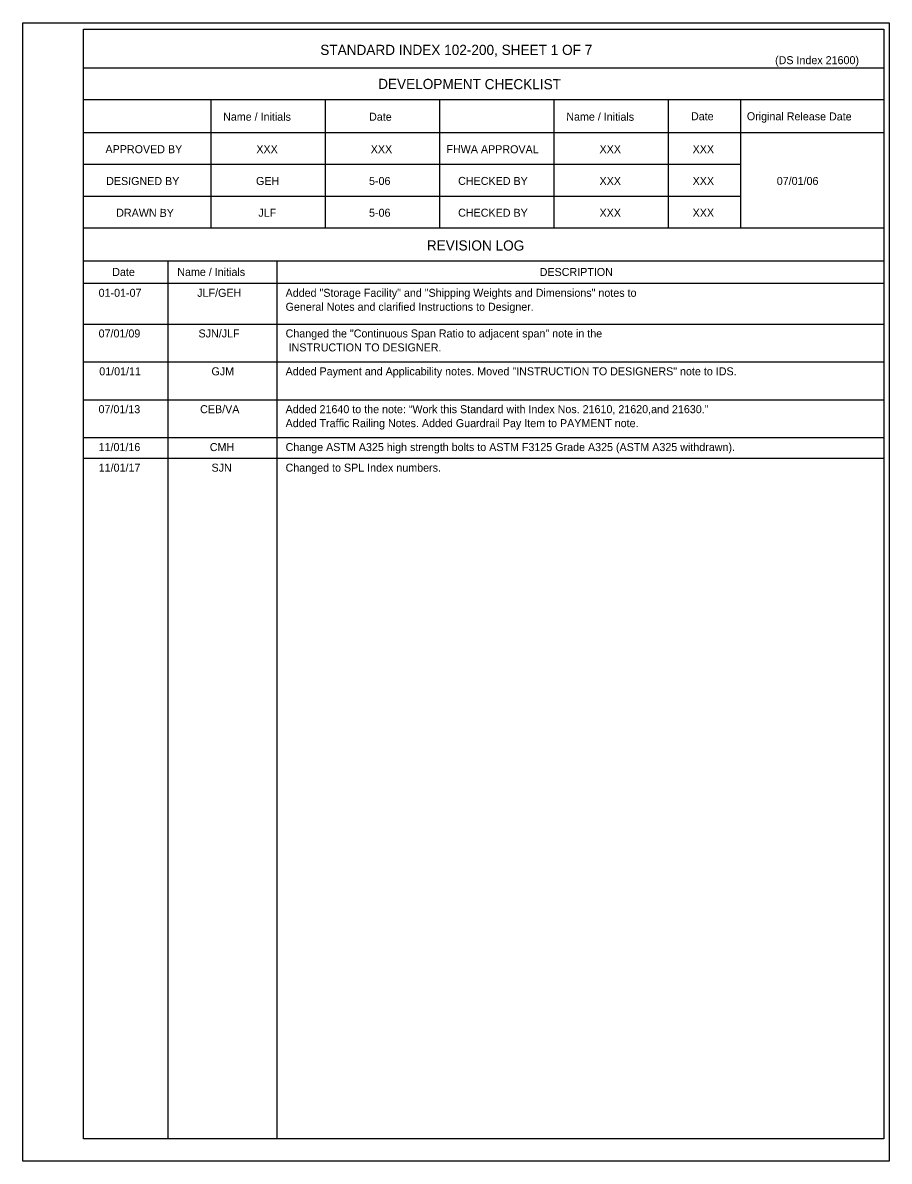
# Model space of a CAD drawing. Extents: x 0 to 2.25, y -0.21 to 0.88.
# Drawn here: x 1.572 to 2.254, y -0.02 to 0.875 of the extents above; entities that cross this region are included whole.
import ezdxf

# ---------------------------------------------------------------- set-up
doc = ezdxf.new("R2010")
doc.units = 0
for name, color, linetype in [('Border', 7, 'Continuous'), ('Dimension', 7, 'Continuous'), ('PlotBorder_dp', 7, 'Continuous'), ('TextStructures', 7, 'Continuous')]:
    doc.layers.add(name, color=color, linetype=linetype)

msp = doc.modelspace()

# ---------------------------------------------------------------- linework, layer by layer
at = {"layer": 'Border'}
for p, q in [((2.24963, 0.83971), (1.62004, 0.83971)), ((2.24963, 0.81471), (1.62004, 0.81471)), ((1.72004, 0.81471), (1.72004, 0.71384)), ((1.81004, 0.81471), (1.81004, 0.71384)), ((1.90004, 0.81471), (1.90004, 0.71384)), ((1.99004, 0.81471), (1.99004, 0.71384)), ((2.08004, 0.81471), (2.08004, 0.71384)), ((2.13676, 0.81471), (2.13676, 0.71384)), ((2.24963, 0.78884), (1.62004, 0.78884)), ((2.13676, 0.76384), (1.62004, 0.76384)), ((2.13676, 0.73884), (1.62004, 0.73884)), ((2.24963, 0.71384), (1.62004, 0.71384)), ((2.24963, 0.68797), (1.62004, 0.68797)), ((1.6863, 0.68797), (1.6863, -0.00286)), ((1.772, 0.68797), (1.772, -0.00286)), ((2.24963, 0.67035), (1.62004, 0.67035))]:
    msp.add_line(p, q, dxfattribs=at)
msp.add_lwpolyline([(1.62005, 0.87035), (2.24963, 0.87035), (2.24963, -0.00286), (1.62005, -0.00286)], close=True, dxfattribs=at)
at = {"layer": 'Dimension'}
for p, q in [((1.62005, 0.63838), (2.24963, 0.63838)), ((1.62005, 0.60858), (2.24963, 0.60858)), ((1.62005, 0.57878), (2.24963, 0.57878)), ((1.62005, 0.54897), (2.24963, 0.54897)), ((1.62005, 0.53277), (2.24963, 0.53277))]:
    msp.add_line(p, q, dxfattribs=at)
at = {"layer": 'PlotBorder_dp'}
msp.add_line((1.57221, -0.0204), (1.57221, -0.0204), dxfattribs=at)
msp.add_lwpolyline([(1.57221, 0.87543), (2.25388, 0.87543), (2.25388, -0.0204), (1.57221, -0.0204)], close=True, dxfattribs=at)

# ---------------------------------------------------------------- texts
at = {"layer": 'TextStructures'}
for s, height, p in [('STANDARD INDEX 102-200, SHEET 1 OF 7', 0.008, (1.80626, 0.8501)), ('(DS Index 21600)', 0.0063, (2.16407, 0.84285)), ('XXX', 0.0063, (1.75598, 0.7728)), ('XXX', 0.0063, (1.84598, 0.7728)), ('XXX', 0.0063, (2.02598, 0.7728)), ('XXX', 0.0063, (2.09921, 0.7728)), ('GEH', 0.0063, (1.75573, 0.7478)), ('5-06', 0.0063, (1.84463, 0.7478)), ('XXX', 0.0063, (2.02598, 0.7478)), ('XXX', 0.0063, (2.09921, 0.7478)), ('07/01/06', 0.0063, (2.1654, 0.7478)), ('JLF', 0.0063, (1.75753, 0.7228)), ('5-06', 0.0063, (1.84463, 0.7228)), ('XXX', 0.0063, (2.02598, 0.7228)), ('XXX', 0.0063, (2.09921, 0.7228)), ('DESCRIPTION', 0.0063, (1.9789, 0.67619)), ('01-01-07', 0.0063, (1.63189, 0.65979)), ('JLF/GEH', 0.0063, (1.70947, 0.65979)), ('Added "Storage Facility" and "Shipping Weights and Dimensions" notes to ', 0.0063, (1.77898, 0.65979)), ('General Notes and clarified Instructions to Designer. ', 0.0063, (1.77898, 0.6488)), ('07/01/09', 0.0063, (1.63189, 0.62782)), ('SJN/JLF', 0.0063, (1.71049, 0.62782)), ('Changed the "Continuous Span Ratio to adjacent span" note in the ', 0.0063, (1.77899, 0.62782)), (' INSTRUCTION TO DESIGNER.', 0.0063, (1.77899, 0.61683)), ('01/01/11', 0.0063, (1.63239, 0.59802)), ('GJM', 0.0063, (1.72066, 0.59802)), ('Added Payment and Applicability notes. Moved "INSTRUCTION TO DESIGNERS" note to IDS.', 0.0063, (1.77899, 0.59802)), ('07/01/13', 0.0063, (1.63182, 0.56821)), ('CEB/VA', 0.0063, (1.71174, 0.56821)), ('Added 21640 to the note: “Work this Standard with Index Nos. 21610, 21620,and 21630.”', 0.0063, (1.77899, 0.56821)), ('Added Traffic Railing Notes. Added Guardrail Pay Item to PAYMENT note.', 0.0063, (1.77899, 0.55722)), ('11/01/16', 0.0063, (1.63189, 0.53841)), ('CMH', 0.0063, (1.71937, 0.53841)), ('Change ASTM A325 high strength bolts to ASTM F3125 Grade A325 (ASTM A325 withdrawn).', 0.0063, (1.77899, 0.53841)), ('11/01/17', 0.0063, (1.63196, 0.52221)), ('SJN', 0.0063, (1.72071, 0.52221)), ('Changed to SPL Index numbers.', 0.0063, (1.77899, 0.52221))]:
    msp.add_text(s, height=height, dxfattribs=at).set_placement(p)
for s, height, p in [('DEVELOPMENT CHECKLIST', 0.008, (1.85179, 0.82336)), ('Name / Initials', 0.0063, (1.72981, 0.79843)), ('Date', 0.0063, (1.84464, 0.79838)), ('Name / Initials', 0.0063, (1.99981, 0.79843)), ('Date', 0.0063, (2.09792, 0.79874)), ('Original Release Date', 0.0063, (2.14188, 0.79874)), ('APPROVED BY', 0.0063, (1.63728, 0.77286)), ('FHWA APPROVAL', 0.0063, (1.90551, 0.77286)), ('DESIGNED BY', 0.0063, (1.63781, 0.74781)), ('CHECKED BY', 0.0063, (1.91473, 0.74786)), ('DRAWN BY', 0.0063, (1.64571, 0.7228)), ('CHECKED BY', 0.0063, (1.91473, 0.72286)), ('REVISION LOG', 0.008, (1.89007, 0.6963)), ('Date', 0.0063, (1.64261, 0.67621)), ('Name / Initials', 0.0063, (1.69376, 0.67626))]:
    msp.add_text(s, height=height, rotation=359.87563, dxfattribs=at).set_placement(p)

doc.saveas('drawing.dxf')
